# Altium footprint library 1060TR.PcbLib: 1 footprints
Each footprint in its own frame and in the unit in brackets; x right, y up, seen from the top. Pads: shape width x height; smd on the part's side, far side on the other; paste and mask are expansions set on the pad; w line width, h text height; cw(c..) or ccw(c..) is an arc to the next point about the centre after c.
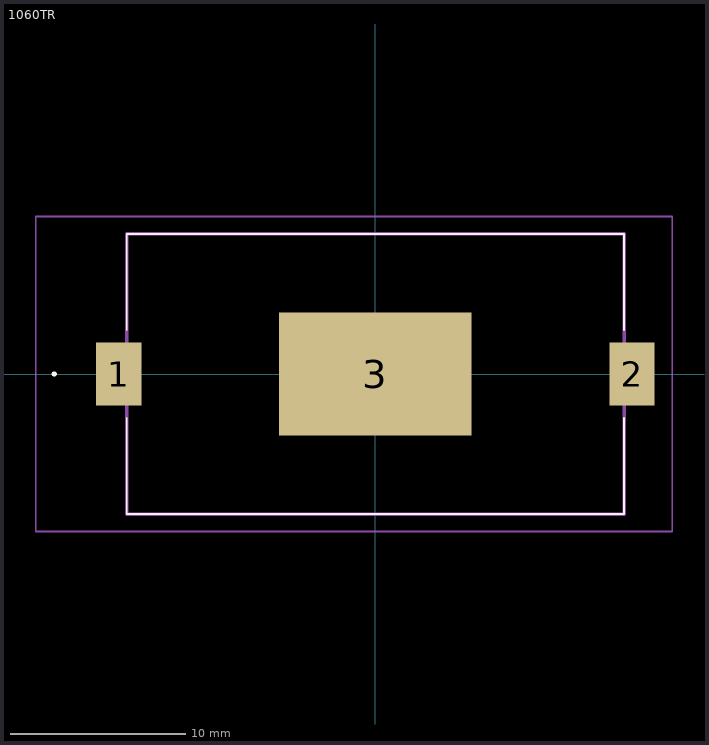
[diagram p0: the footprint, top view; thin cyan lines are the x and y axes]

## 1060TR [mm]
pads (3):
  rect 2.59x3.61 smd: 1(-14.655,0) 2(14.655,0)
  rect 11x7.01 smd: 3(0,0)
Top Overlay:
  lines w0.1: -14.2,-8 14.2,-8 ; -14.2,-8 -14.2,-8 ; -14.2,-8 14.2,-8 ; -14.2,-8 -14.2,-8 ; -14.2,-8 -14.2,-2.5 ; -14.2,-8 -14.2,-2.5 ; -14.2,-2.5 -14.2,-2.5 ; -14.2,2.5 -14.2,2.5 ; -14.2,2.5 -14.2,8 ; -14.2,2.5 -14.2,8 ; -14.2,8 14.2,8 ; -14.2,8 14.2,8 ; -14.2,8 -14.2,8 ; -14.2,8 -14.2,8 ; 14.2,-8 14.2,-8 ; 14.2,-8 14.2,-2.5 ; 14.2,-8 14.2,-8 ; 14.2,-8 14.2,-2.5 ; 14.2,-2.5 14.2,-2.5 ; 14.2,2.5 14.2,8 ; 14.2,2.5 14.2,2.5 ; 14.2,2.5 14.2,8 ; 14.2,8 14.2,8 ; 14.2,8 14.2,8
  lines w0.2: -18.4,0 -18.4,0 ; -18.4,0 ccw(c-18.35,0) -18.3,0 ; -18.4,0 cw(c-18.35,0) -18.3,0 ; -18.4,0 -18.4,0 ; -18.4,0 ccw(c-18.35,0) -18.3,0 ; -18.3,0 -18.3,0
Mechanical 15:
  lines w0.2: -14.2,-8 14.2,-8 14.2,8 -14.2,8 -14.2,-8
Mechanical 20:
  lines w0.1: -19.4,-9 16.95,-9 16.95,9 -19.4,9 -19.4,-9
